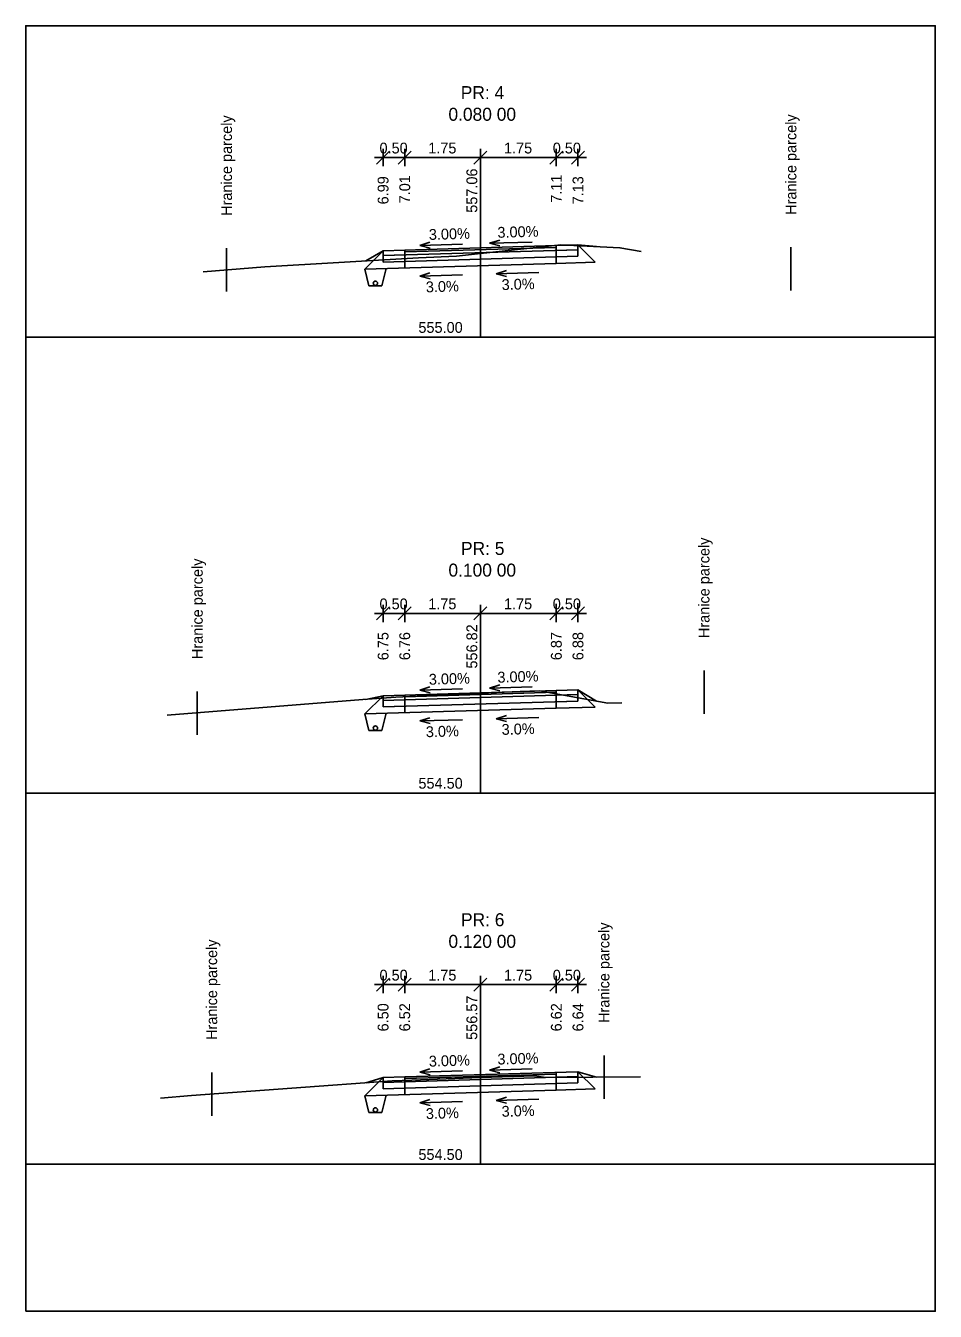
# Model space of a CAD drawing. Extents: x -603737 to -603383, y -1112154 to -1112124.
# Drawn here: x -603687.65 to -603666.65, y -1112153.84 to -1112124.14 of the extents above; entities that cross this region are included whole.
import ezdxf

# ---------------------------------------------------------------- set-up
doc = ezdxf.new("R2010")
doc.units = 0
for name, color, linetype in [('_křivky z hran', 7, 'Continuous'), ('_netisk', 7, 'Continuous'), ('C3D_Podsestava-Popis', 7, 'Continuous'), ('C3D_PP-Popisek', 7, 'Continuous'), ('C3D_PR', 7, 'Continuous'), ('C3D_ZPR', 7, 'Continuous'), ('Default', 7, 'Continuous'), ('konstrukce', 7, 'Continuous')]:
    doc.layers.add(name, color=color, linetype=linetype)

# ---------------------------------------------------------------- blocks, each defined once
blk = doc.blocks.new('_Oblique')
at = {"layer": 'Default'}
blk.add_line((-0.5, -0.5), (0.5, 0.5), dxfattribs=at)
blk = doc.blocks.new('AeccTickLine')
at = {"layer": 'Default'}
blk.add_line((0, 1), (0, -1), dxfattribs=at)

msp = doc.modelspace()

# ---------------------------------------------------------------- linework, layer by layer
at = {"layer": '_netisk'}
msp.add_lwpolyline([(-603687.651, -1112153.84), (-603666.651, -1112153.84), (-603666.651, -1112124.14), (-603687.651, -1112124.14)], close=True, dxfattribs=at)
at = {"layer": 'C3D_Podsestava-Popis'}
for p, q in [((-603679.601, -1112127.186), (-603677.151, -1112127.186)), ((-603677.151, -1112127.186), (-603674.701, -1112127.186)), ((-603679.401, -1112127.341), (-603679.401, -1112127.336)), ((-603678.901, -1112127.336), (-603678.901, -1112127.326)), ((-603677.151, -1112127.336), (-603677.151, -1112127.274)), ((-603675.401, -1112127.336), (-603675.401, -1112127.221)), ((-603674.901, -1112127.206), (-603674.901, -1112127.336)), ((-603677.151, -1112137.867), (-603677.151, -1112137.551)), ((-603675.401, -1112137.867), (-603675.401, -1112137.498)), ((-603674.901, -1112137.483), (-603674.901, -1112137.867)), ((-603679.601, -1112137.717), (-603677.151, -1112137.717)), ((-603679.401, -1112137.618), (-603679.401, -1112137.867)), ((-603678.901, -1112137.867), (-603678.901, -1112137.603)), ((-603677.151, -1112137.717), (-603674.701, -1112137.717)), ((-603679.601, -1112146.294), (-603677.151, -1112146.294)), ((-603679.401, -1112146.441), (-603679.401, -1112146.444)), ((-603678.901, -1112146.444), (-603678.901, -1112146.426)), ((-603677.151, -1112146.294), (-603674.701, -1112146.294)), ((-603677.151, -1112146.444), (-603677.151, -1112146.373)), ((-603675.401, -1112146.444), (-603675.401, -1112146.321)), ((-603674.901, -1112146.306), (-603674.901, -1112146.444))]:
    msp.add_line(p, q, dxfattribs=at)
at = {"layer": 'C3D_PP-Popisek'}
for p, q in [((-603678.554, -1112129.216), (-603678.317, -1112129.141)), ((-603677.57, -1112129.187), (-603678.554, -1112129.216)), ((-603678.554, -1112129.216), (-603678.313, -1112129.277)), ((-603676.942, -1112129.167), (-603676.706, -1112129.092)), ((-603675.959, -1112129.138), (-603676.942, -1112129.167)), ((-603676.942, -1112129.167), (-603676.702, -1112129.229)), ((-603678.554, -1112129.926), (-603678.317, -1112129.851)), ((-603676.789, -1112129.873), (-603676.552, -1112129.798)), ((-603675.805, -1112129.844), (-603676.789, -1112129.873)), ((-603677.57, -1112129.897), (-603678.554, -1112129.926)), ((-603678.554, -1112129.926), (-603678.313, -1112129.987)), ((-603676.789, -1112129.873), (-603676.548, -1112129.934)), ((-603676.942, -1112139.444), (-603676.706, -1112139.369)), ((-603678.554, -1112139.493), (-603678.317, -1112139.417)), ((-603677.57, -1112139.463), (-603678.554, -1112139.493)), ((-603678.554, -1112139.493), (-603678.313, -1112139.554)), ((-603675.959, -1112139.415), (-603676.942, -1112139.444)), ((-603676.942, -1112139.444), (-603676.702, -1112139.505)), ((-603678.554, -1112140.203), (-603678.317, -1112140.127)), ((-603677.57, -1112140.173), (-603678.554, -1112140.203)), ((-603678.554, -1112140.203), (-603678.313, -1112140.264)), ((-603676.789, -1112140.15), (-603676.552, -1112140.074)), ((-603675.805, -1112140.12), (-603676.789, -1112140.15)), ((-603676.789, -1112140.15), (-603676.548, -1112140.211)), ((-603678.554, -1112148.316), (-603678.317, -1112148.24)), ((-603676.942, -1112148.267), (-603676.706, -1112148.192)), ((-603675.959, -1112148.237), (-603676.942, -1112148.267)), ((-603676.942, -1112148.267), (-603676.702, -1112148.328)), ((-603677.57, -1112148.286), (-603678.554, -1112148.316)), ((-603678.554, -1112148.316), (-603678.313, -1112148.377)), ((-603678.554, -1112149.026), (-603678.317, -1112148.95)), ((-603677.57, -1112148.996), (-603678.554, -1112149.026)), ((-603678.554, -1112149.026), (-603678.313, -1112149.087)), ((-603676.789, -1112148.973), (-603676.552, -1112148.897)), ((-603675.805, -1112148.943), (-603676.789, -1112148.973)), ((-603676.789, -1112148.973), (-603676.548, -1112149.034))]:
    msp.add_line(p, q, dxfattribs=at)
at = {"layer": 'C3D_PR'}
for points in [[(-603683.551, -1112129.826), (-603682.133, -1112129.713), (-603678.585, -1112129.5), (-603677.708, -1112129.461), (-603677.151, -1112129.4), (-603675.296, -1112129.199), (-603673.93, -1112129.271), (-603673.438, -1112129.358)], [(-603684.387, -1112140.071), (-603679.864, -1112139.708), (-603679.109, -1112139.653), (-603677.151, -1112139.563), (-603676.232, -1112139.521), (-603675.789, -1112139.505), (-603674.21, -1112139.79), (-603673.887, -1112139.787)], [(-603684.538, -1112148.914), (-603683.824, -1112148.857), (-603679.192, -1112148.519), (-603678.737, -1112148.498), (-603677.151, -1112148.442), (-603675.895, -1112148.397), (-603675.653, -1112148.44), (-603673.455, -1112148.423)]]:
    msp.add_lwpolyline(points, dxfattribs=at)
at = {"layer": 'C3D_ZPR'}
for p, q in [((-603677.151, -1112131.336), (-603677.151, -1112127.336)), ((-603678.901, -1112129.326), (-603674.901, -1112129.206)), ((-603678.901, -1112129.366), (-603675.401, -1112129.261)), ((-603675.401, -1112129.261), (-603675.401, -1112129.221)), ((-603675.401, -1112129.631), (-603675.401, -1112129.221)), ((-603674.901, -1112129.466), (-603674.901, -1112129.206)), ((-603674.901, -1112129.466), (-603674.901, -1112129.206)), ((-603674.901, -1112129.206), (-603674.503, -1112129.605)), ((-603674.901, -1112129.206), (-603674.476, -1112129.242)), ((-603674.901, -1112129.206), (-603674.476, -1112129.242)), ((-603669.982, -1112130.26), (-603669.982, -1112129.26)), ((-603683.013, -1112130.283), (-603683.013, -1112129.283)), ((-603679.823, -1112129.764), (-603679.401, -1112129.341)), ((-603679.401, -1112129.341), (-603679.796, -1112129.573)), ((-603679.796, -1112129.573), (-603679.401, -1112129.341)), ((-603679.401, -1112129.451), (-603674.901, -1112129.316)), ((-603679.401, -1112129.341), (-603678.901, -1112129.326)), ((-603679.401, -1112129.601), (-603679.401, -1112129.341)), ((-603679.401, -1112129.601), (-603679.401, -1112129.341)), ((-603679.401, -1112129.451), (-603678.901, -1112129.436)), ((-603679.401, -1112129.601), (-603674.901, -1112129.466)), ((-603678.901, -1112129.736), (-603678.901, -1112129.326)), ((-603678.901, -1112129.436), (-603678.901, -1112129.366)), ((-603675.401, -1112129.331), (-603674.901, -1112129.316)), ((-603675.401, -1112129.481), (-603675.401, -1112129.331)), ((-603675.401, -1112129.481), (-603674.901, -1112129.466)), ((-603679.823, -1112129.764), (-603675.401, -1112129.631)), ((-603679.401, -1112129.601), (-603678.901, -1112129.586)), ((-603678.901, -1112129.736), (-603678.901, -1112129.586)), ((-603675.401, -1112129.631), (-603674.503, -1112129.605)), ((-603687.651, -1112131.336), (-603666.651, -1112131.336)), ((-603677.151, -1112141.867), (-603677.151, -1112137.867)), ((-603671.989, -1112140.038), (-603671.989, -1112139.038)), ((-603683.689, -1112140.523), (-603683.689, -1112139.523)), ((-603679.823, -1112140.041), (-603679.401, -1112139.618)), ((-603679.401, -1112139.618), (-603679.796, -1112139.703)), ((-603679.796, -1112139.703), (-603679.401, -1112139.618)), ((-603679.401, -1112139.728), (-603674.901, -1112139.593)), ((-603679.401, -1112139.618), (-603678.901, -1112139.603)), ((-603679.401, -1112139.878), (-603679.401, -1112139.618)), ((-603679.401, -1112139.878), (-603679.401, -1112139.618)), ((-603678.901, -1112139.603), (-603674.901, -1112139.483)), ((-603678.901, -1112139.643), (-603675.401, -1112139.538)), ((-603678.901, -1112140.013), (-603678.901, -1112139.603)), ((-603678.901, -1112139.713), (-603678.901, -1112139.643)), ((-603675.401, -1112139.538), (-603675.401, -1112139.498)), ((-603675.401, -1112139.908), (-603675.401, -1112139.498)), ((-603675.401, -1112139.608), (-603674.901, -1112139.593)), ((-603675.401, -1112139.758), (-603675.401, -1112139.608)), ((-603674.901, -1112139.743), (-603674.901, -1112139.483)), ((-603674.901, -1112139.743), (-603674.901, -1112139.483)), ((-603674.901, -1112139.483), (-603674.503, -1112139.881)), ((-603674.901, -1112139.483), (-603674.476, -1112139.742)), ((-603674.901, -1112139.483), (-603674.476, -1112139.742)), ((-603679.823, -1112140.041), (-603675.401, -1112139.908)), ((-603679.401, -1112139.728), (-603678.901, -1112139.713)), ((-603679.401, -1112139.878), (-603674.901, -1112139.743)), ((-603679.401, -1112139.878), (-603678.901, -1112139.863)), ((-603678.901, -1112140.013), (-603678.901, -1112139.863)), ((-603675.401, -1112139.758), (-603674.901, -1112139.743)), ((-603675.401, -1112139.908), (-603674.503, -1112139.881)), ((-603687.651, -1112141.867), (-603666.651, -1112141.867)), ((-603677.151, -1112150.444), (-603677.151, -1112146.444)), ((-603674.299, -1112148.93), (-603674.299, -1112147.93)), ((-603683.356, -1112149.322), (-603683.356, -1112148.322)), ((-603679.823, -1112148.864), (-603679.401, -1112148.441)), ((-603679.401, -1112148.441), (-603679.796, -1112148.563)), ((-603679.796, -1112148.563), (-603679.401, -1112148.441)), ((-603679.401, -1112148.551), (-603674.901, -1112148.416)), ((-603679.401, -1112148.441), (-603678.901, -1112148.426)), ((-603679.401, -1112148.701), (-603679.401, -1112148.441)), ((-603679.401, -1112148.701), (-603679.401, -1112148.441)), ((-603679.401, -1112148.551), (-603678.901, -1112148.536)), ((-603679.401, -1112148.701), (-603674.901, -1112148.566)), ((-603678.901, -1112148.426), (-603674.901, -1112148.306)), ((-603678.901, -1112148.466), (-603675.401, -1112148.361)), ((-603678.901, -1112148.836), (-603678.901, -1112148.426)), ((-603678.901, -1112148.536), (-603678.901, -1112148.466)), ((-603675.401, -1112148.361), (-603675.401, -1112148.321)), ((-603675.401, -1112148.731), (-603675.401, -1112148.321)), ((-603675.401, -1112148.431), (-603674.901, -1112148.416)), ((-603675.401, -1112148.581), (-603675.401, -1112148.431)), ((-603675.401, -1112148.581), (-603674.901, -1112148.566)), ((-603674.901, -1112148.566), (-603674.901, -1112148.306)), ((-603674.901, -1112148.566), (-603674.901, -1112148.306)), ((-603674.503, -1112148.704), (-603674.901, -1112148.306)), ((-603674.901, -1112148.306), (-603674.476, -1112148.431)), ((-603674.901, -1112148.306), (-603674.476, -1112148.431)), ((-603679.823, -1112148.864), (-603675.401, -1112148.731)), ((-603679.401, -1112148.701), (-603678.901, -1112148.686)), ((-603678.901, -1112148.836), (-603678.901, -1112148.686)), ((-603675.401, -1112148.731), (-603674.503, -1112148.704)), ((-603687.651, -1112150.444), (-603666.651, -1112150.444))]:
    msp.add_line(p, q, dxfattribs=at)
at = {"layer": 'konstrukce'}
for p, q in [((-603679.727, -1112130.149), (-603679.823, -1112129.764)), ((-603679.427, -1112130.149), (-603679.327, -1112129.749)), ((-603679.427, -1112130.149), (-603679.727, -1112130.149)), ((-603679.727, -1112140.426), (-603679.823, -1112140.041)), ((-603679.427, -1112140.426), (-603679.327, -1112140.026)), ((-603679.427, -1112140.426), (-603679.727, -1112140.426)), ((-603679.727, -1112149.249), (-603679.823, -1112148.864)), ((-603679.427, -1112149.249), (-603679.327, -1112148.849)), ((-603679.427, -1112149.249), (-603679.727, -1112149.249))]:
    msp.add_line(p, q, dxfattribs=at)
for centre in [(-603679.577, -1112130.089), (-603679.577, -1112140.366), (-603679.577, -1112149.189)]:
    msp.add_circle(centre, 0.05, dxfattribs=at)

# ---------------------------------------------------------------- block references
at = {"layer": '_křivky z hran', "rotation": 180}
for name, p, xscale, yscale in [('_Oblique', (-603679.401, -1112127.186), 0.3, 0.3), ('AeccTickLine', (-603679.401, -1112127.186), 0.2, 0.20000000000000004), ('_Oblique', (-603678.901, -1112127.186), 0.3, 0.3), ('AeccTickLine', (-603678.901, -1112127.186), 0.2, 0.20000000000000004), ('_Oblique', (-603677.151, -1112127.186), 0.3, 0.3), ('AeccTickLine', (-603677.151, -1112127.186), 0.2, 0.20000000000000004), ('_Oblique', (-603679.401, -1112137.717), 0.3, 0.3), ('AeccTickLine', (-603679.401, -1112137.717), 0.2, 0.20000000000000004), ('_Oblique', (-603678.901, -1112137.717), 0.3, 0.3), ('AeccTickLine', (-603678.901, -1112137.717), 0.2, 0.20000000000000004), ('_Oblique', (-603677.151, -1112137.717), 0.3, 0.3), ('AeccTickLine', (-603677.151, -1112137.717), 0.2, 0.20000000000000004), ('_Oblique', (-603679.401, -1112146.294), 0.3, 0.3), ('AeccTickLine', (-603679.401, -1112146.294), 0.2, 0.20000000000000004), ('_Oblique', (-603678.901, -1112146.294), 0.3, 0.3), ('AeccTickLine', (-603678.901, -1112146.294), 0.2, 0.20000000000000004), ('_Oblique', (-603677.151, -1112146.294), 0.3, 0.3), ('AeccTickLine', (-603677.151, -1112146.294), 0.2, 0.20000000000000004)]:
    msp.add_blockref(name, p, dxfattribs=dict(at, xscale=xscale, yscale=yscale))
at = {"layer": '_křivky z hran'}
for name, p, xscale, yscale in [('_Oblique', (-603677.151, -1112127.186), 0.3, 0.3), ('AeccTickLine', (-603677.151, -1112127.186), 0.2, 0.20000000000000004), ('_Oblique', (-603675.401, -1112127.186), 0.3, 0.3), ('AeccTickLine', (-603675.401, -1112127.186), 0.2, 0.20000000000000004), ('_Oblique', (-603674.901, -1112127.186), 0.3, 0.3), ('AeccTickLine', (-603674.901, -1112127.186), 0.2, 0.20000000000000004), ('_Oblique', (-603677.151, -1112137.717), 0.3, 0.3), ('AeccTickLine', (-603677.151, -1112137.717), 0.2, 0.20000000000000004), ('_Oblique', (-603675.401, -1112137.717), 0.3, 0.3), ('AeccTickLine', (-603675.401, -1112137.717), 0.2, 0.20000000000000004), ('_Oblique', (-603674.901, -1112137.717), 0.3, 0.3), ('AeccTickLine', (-603674.901, -1112137.717), 0.2, 0.20000000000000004), ('_Oblique', (-603677.151, -1112146.294), 0.3, 0.3), ('AeccTickLine', (-603677.151, -1112146.294), 0.2, 0.20000000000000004), ('_Oblique', (-603675.401, -1112146.294), 0.3, 0.3), ('AeccTickLine', (-603675.401, -1112146.294), 0.2, 0.20000000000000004), ('_Oblique', (-603674.901, -1112146.294), 0.3, 0.3), ('AeccTickLine', (-603674.901, -1112146.294), 0.2, 0.20000000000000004)]:
    msp.add_blockref(name, p, dxfattribs=dict(at, xscale=xscale, yscale=yscale))

# ---------------------------------------------------------------- texts
at = {"layer": 'C3D_Podsestava-Popis'}
for s, rotation, p in [('0.50', 360, (-603679.482, -1112127.092)), ('1.75', 360, (-603678.358, -1112127.092)), ('1.75', 360, (-603678.358, -1112127.092)), ('1.75', 360, (-603676.608, -1112127.092)), ('1.75', 360, (-603676.608, -1112127.092)), ('0.50', 360, (-603675.482, -1112127.092)), ('557.06', 90, (-603677.225, -1112128.462)), ('6.99', 90, (-603679.275, -1112128.268)), ('6.99', 90, (-603679.275, -1112128.268)), ('7.01', 90, (-603678.775, -1112128.244)), ('7.11', 90, (-603675.275, -1112128.231)), ('7.13', 90, (-603674.775, -1112128.268)), ('7.13', 90, (-603674.775, -1112128.268)), ('3.00%', 1.7184, (-603678.34, -1112129.09)), ('3.00%', 1.7184, (-603676.756, -1112129.041)), ('3.0%', 1.7184, (-603678.409, -1112130.301)), ('3.0%', 1.7184, (-603676.659, -1112130.248)), ('0.50', 360, (-603679.482, -1112137.623)), ('1.75', 360, (-603678.358, -1112137.623)), ('1.75', 360, (-603678.358, -1112137.623)), ('1.75', 360, (-603676.608, -1112137.623)), ('1.75', 360, (-603676.608, -1112137.623)), ('0.50', 360, (-603675.482, -1112137.623)), ('6.75', 90, (-603679.275, -1112138.8)), ('6.75', 90, (-603679.275, -1112138.8)), ('6.76', 90, (-603678.775, -1112138.799)), ('556.82', 90, (-603677.225, -1112138.992)), ('6.87', 90, (-603675.275, -1112138.799)), ('6.88', 90, (-603674.775, -1112138.799)), ('6.88', 90, (-603674.775, -1112138.799)), ('3.00%', 1.7184, (-603676.756, -1112139.318)), ('3.00%', 1.7184, (-603678.34, -1112139.366)), ('3.0%', 1.7184, (-603676.659, -1112140.525)), ('3.0%', 1.7184, (-603678.409, -1112140.578)), ('0.50', 360, (-603679.482, -1112146.2)), ('1.75', 360, (-603678.358, -1112146.2)), ('1.75', 360, (-603678.358, -1112146.2)), ('1.75', 360, (-603676.608, -1112146.2)), ('1.75', 360, (-603676.608, -1112146.2)), ('0.50', 360, (-603675.482, -1112146.2)), ('6.50', 90, (-603679.275, -1112147.375)), ('6.50', 90, (-603679.275, -1112147.375)), ('6.52', 90, (-603678.775, -1112147.374)), ('556.57', 90, (-603677.225, -1112147.57)), ('6.62', 90, (-603675.275, -1112147.374)), ('6.64', 90, (-603674.775, -1112147.375)), ('6.64', 90, (-603674.775, -1112147.375)), ('3.00%', 1.7184, (-603678.34, -1112148.189)), ('3.00%', 1.7184, (-603676.756, -1112148.141)), ('3.0%', 1.7184, (-603678.409, -1112149.4)), ('3.0%', 1.7184, (-603676.659, -1112149.348))]:
    msp.add_text(s, height=0.25, rotation=rotation, dxfattribs=at).set_placement(p)
at = {"layer": 'C3D_ZPR'}
for s, p in [('PR: 4', (-603677.606, -1112125.836)), ('0.080 00', (-603677.891, -1112126.336)), ('PR: 5', (-603677.601, -1112136.367)), ('0.100 00', (-603677.891, -1112136.867)), ('PR: 6', (-603677.601, -1112144.944)), ('0.120 00', (-603677.891, -1112145.444))]:
    msp.add_text(s, height=0.3, dxfattribs=at).set_placement(p)
for s, rotation, p in [('Hranice parcely', 90, (-603682.888, -1112128.533)), ('Hranice parcely', 90, (-603669.857, -1112128.51)), ('555.00', 360, (-603678.584, -1112131.236)), ('Hranice parcely', 90, (-603671.864, -1112138.288)), ('Hranice parcely', 90, (-603683.564, -1112138.773)), ('554.50', 360, (-603678.584, -1112141.767)), ('Hranice parcely', 90, (-603674.174, -1112147.18)), ('Hranice parcely', 90, (-603683.231, -1112147.572)), ('554.50', 360, (-603678.584, -1112150.344))]:
    msp.add_text(s, height=0.25, rotation=rotation, dxfattribs=at).set_placement(p)

doc.saveas('drawing.dxf')
